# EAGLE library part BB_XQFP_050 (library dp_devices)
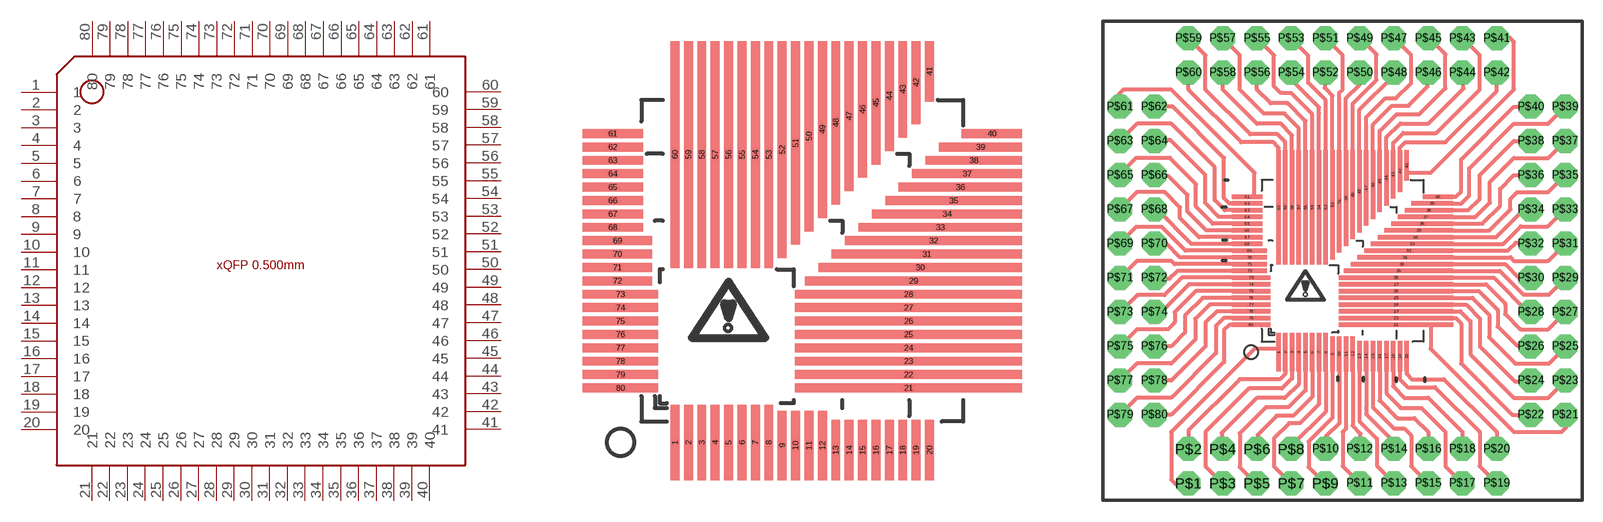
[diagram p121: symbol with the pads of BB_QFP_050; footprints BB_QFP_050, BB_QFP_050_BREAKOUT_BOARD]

Designator prefix -

## BB_XQFP_050  [BB_QFP_050]
1  1
2  2
3  3
4  4
5  5
6  6
7  7
8  8
9  9
10  10
11  11
12  12
13  13
14  14
15  15
16  16
17  17
18  18
19  19
20  20
21  21
22  22
23  23
24  24
25  25
26  26
27  27
28  28
29  29
30  30
31  31
32  32
33  33
34  34
35  35
36  36
37  37
38  38
39  39
40  40
41  41
42  42
43  43
44  44
45  45
46  46
47  47
48  48
49  49
50  50
51  51
52  52
53  53
54  54
55  55
56  56
57  57
58  58
59  59
60  60
61  61
62  62
63  63
64  64
65  65
66  66
67  67
68  68
69  69
70  70
71  71
72  72
73  73
74  74
75  75
76  76
77  77
78  78
79  79
80  80

## BB_XQFP_050BB  [BB_QFP_050_BREAKOUT_BOARD]
P$1  1
P$2  2
P$3  3
P$4  4
P$5  5
P$6  6
P$7  7
P$8  8
P$9  9
P$10  10
P$11  11
P$12  12
P$13  13
P$14  14
P$15  15
P$16  16
P$17  17
P$18  18
P$19  19
P$20  20
P$21  21
P$22  22
P$23  23
P$24  24
P$25  25
P$26  26
P$27  27
P$28  28
P$29  29
P$30  30
P$31  31
P$32  32
P$33  33
P$34  34
P$35  35
P$36  36
P$37  37
P$38  38
P$39  39
P$40  40
P$41  41
P$42  42
P$43  43
P$44  44
P$45  45
P$46  46
P$47  47
P$48  48
P$49  49
P$50  50
P$51  51
P$52  52
P$53  53
P$54  54
P$55  55
P$56  56
P$57  57
P$58  58
P$59  59
P$60  60
P$61  61
P$62  62
P$63  63
P$64  64
P$65  65
P$66  66
P$67  67
P$68  68
P$69  69
P$70  70
P$71  71
P$72  72
P$73  73
P$74  74
P$75  75
P$76  76
P$77  77
P$78  78
P$79  79
P$80  80

## Footprint BB_QFP_050 (pad centres in mm)
QFP 0.5 mm pitch 32p (5mm sq) 48p (7mm sq) 64p (10mm sq) 80p (12mm sq) CC-BY-SA
smd 0.33 x 2.824: 1 -4.75,-6.788; 2 -4.25,-6.788; 3 -3.75,-6.788; 4 -3.25,-6.788; 5 -2.75,-6.788; 6 -2.25,-6.788; 7 -1.75,-6.788; 8 -1.25,-6.788
smd 0.33 x 2.6: 9 -0.75,-6.9; 10 -0.25,-6.9; 11 0.25,-6.9; 12 0.75,-6.9
smd 0.33 x 2.25: 13 1.25,-7.075; 14 1.75,-7.075; 15 2.25,-7.075; 16 2.75,-7.075; 17 3.25,-7.075; 18 3.75,-7.075; 19 4.25,-7.075; 20 4.75,-7.075; 41 4.75,7.075
smd 8.47 x 0.33: 21 3.965,-4.75; 22 3.965,-4.25; 23 3.965,-3.75; 24 3.965,-3.25; 25 3.965,-2.75; 26 3.965,-2.25; 27 3.965,-1.75; 28 3.965,-1.25
smd 8.1 x 0.33: 29 4.15,-0.75
smd 7.6 x 0.33: 30 4.4,-0.25
smd 7.1 x 0.33: 31 4.65,0.25
smd 6.6 x 0.33: 32 4.9,0.75
smd 6.1 x 0.33: 33 5.15,1.25
smd 5.6 x 0.33: 34 5.4,1.75
smd 5.1 x 0.33: 35 5.65,2.25
smd 4.6 x 0.33: 36 5.9,2.75
smd 4.1 x 0.33: 37 6.15,3.25
smd 3.6 x 0.33: 38 6.4,3.75
smd 3.1 x 0.33: 39 6.65,4.25
smd 2.25 x 0.33: 40 7.075,4.75; 61 -7.075,4.75; 62 -7.075,4.25; 63 -7.075,3.75; 64 -7.075,3.25; 65 -7.075,2.75; 66 -7.075,2.25; 67 -7.075,1.75; 68 -7.075,1.25
smd 0.33 x 3.1: 42 4.25,6.65
smd 0.33 x 3.6: 43 3.75,6.4
smd 0.33 x 4.1: 44 3.25,6.15
smd 0.33 x 4.6: 45 2.75,5.9
smd 0.33 x 5.1: 46 2.25,5.65
smd 0.33 x 5.6: 47 1.75,5.4
smd 0.33 x 6.1: 48 1.25,5.15
smd 0.33 x 6.6: 49 0.75,4.9
smd 0.33 x 7.1: 50 0.25,4.65
smd 0.33 x 7.6: 51 -0.25,4.4
smd 0.33 x 8.1: 52 -0.75,4.15
smd 0.33 x 8.47: 53 -1.25,3.965; 54 -1.75,3.965; 55 -2.25,3.965; 56 -2.75,3.965; 57 -3.25,3.965; 58 -3.75,3.965; 59 -4.25,3.965; 60 -4.75,3.965
smd 2.6 x 0.33: 69 -6.9,0.75; 70 -6.9,0.25; 71 -6.9,-0.25; 72 -6.9,-0.75
smd 2.824 x 0.33: 73 -6.788,-1.25; 74 -6.788,-1.75; 75 -6.788,-2.25; 76 -6.788,-2.75; 77 -6.788,-3.25; 78 -6.788,-3.75; 79 -6.788,-4.25; 80 -6.788,-4.75

## Footprint BB_QFP_050_BREAKOUT_BOARD (pad centres in mm)
QFP 0.5 mm pitch 32p (5mm sq) 48p (7mm sq) 64p (10mm sq) 80p (12mm sq) CC-BY-SA
smd 0.33 x 2.824: 1 -4.75,-6.788; 2 -4.25,-6.788; 3 -3.75,-6.788; 4 -3.25,-6.788; 5 -2.75,-6.788; 6 -2.25,-6.788; 7 -1.75,-6.788; 8 -1.25,-6.788
smd 0.33 x 2.6: 9 -0.75,-6.9; 10 -0.25,-6.9; 11 0.25,-6.9; 12 0.75,-6.9
smd 0.33 x 2.25: 13 1.25,-7.075; 14 1.75,-7.075; 15 2.25,-7.075; 16 2.75,-7.075; 17 3.25,-7.075; 18 3.75,-7.075; 19 4.25,-7.075; 20 4.75,-7.075; 41 4.75,7.075
smd 8.47 x 0.33: 21 3.965,-4.75; 22 3.965,-4.25; 23 3.965,-3.75; 24 3.965,-3.25; 25 3.965,-2.75; 26 3.965,-2.25; 27 3.965,-1.75; 28 3.965,-1.25
smd 8.1 x 0.33: 29 4.15,-0.75
smd 7.6 x 0.33: 30 4.4,-0.25
smd 7.1 x 0.33: 31 4.65,0.25
smd 6.6 x 0.33: 32 4.9,0.75
smd 6.1 x 0.33: 33 5.15,1.25
smd 5.6 x 0.33: 34 5.4,1.75
smd 5.1 x 0.33: 35 5.65,2.25
smd 4.6 x 0.33: 36 5.9,2.75
smd 4.1 x 0.33: 37 6.15,3.25
smd 3.6 x 0.33: 38 6.4,3.75
smd 3.1 x 0.33: 39 6.65,4.25
smd 2.25 x 0.33: 40 7.075,4.75; 61 -7.075,4.75; 62 -7.075,4.25; 63 -7.075,3.75; 64 -7.075,3.25; 65 -7.075,2.75; 66 -7.075,2.25; 67 -7.075,1.75; 68 -7.075,1.25
smd 0.33 x 3.1: 42 4.25,6.65
smd 0.33 x 3.6: 43 3.75,6.4
smd 0.33 x 4.1: 44 3.25,6.15
smd 0.33 x 4.6: 45 2.75,5.9
smd 0.33 x 5.1: 46 2.25,5.65
smd 0.33 x 5.6: 47 1.75,5.4
smd 0.33 x 6.1: 48 1.25,5.15
smd 0.33 x 6.6: 49 0.75,4.9
smd 0.33 x 7.1: 50 0.25,4.65
smd 0.33 x 7.6: 51 -0.25,4.4
smd 0.33 x 8.1: 52 -0.75,4.15
smd 0.33 x 8.47: 53 -1.25,3.965; 54 -1.75,3.965; 55 -2.25,3.965; 56 -2.75,3.965; 57 -3.25,3.965; 58 -3.75,3.965; 59 -4.25,3.965; 60 -4.75,3.965
smd 2.6 x 0.33: 69 -6.9,0.75; 70 -6.9,0.25; 71 -6.9,-0.25; 72 -6.9,-0.75
smd 2.824 x 0.33: 73 -6.788,-1.25; 74 -6.788,-1.75; 75 -6.788,-2.25; 76 -6.788,-2.75; 77 -6.788,-3.25; 78 -6.788,-3.75; 79 -6.788,-4.25; 80 -6.788,-4.75
drill 1.016 pad 1.778 octagon: P$1 -11.43,-16.51; P$2 -11.43,-13.97; P$3 -8.89,-16.51; P$4 -8.89,-13.97; P$5 -6.35,-16.51; P$6 -6.35,-13.97; P$7 -3.81,-16.51; P$8 -3.81,-13.97; P$9 -1.27,-16.51; P$10 -1.27,-13.97; P$11 1.27,-16.51; P$12 1.27,-13.97; P$13 3.81,-16.51; P$14 3.81,-13.97; P$15 6.35,-16.51; P$16 6.35,-13.97; P$17 8.89,-16.51; P$18 8.89,-13.97; P$19 11.43,-16.51; P$20 11.43,-13.97; P$21 16.51,-11.43; P$22 13.97,-11.43; P$23 16.51,-8.89; P$24 13.97,-8.89; P$25 16.51,-6.35; P$26 13.97,-6.35; P$27 16.51,-3.81; P$28 13.97,-3.81; P$29 16.51,-1.27; P$30 13.97,-1.27; P$31 16.51,1.27; P$32 13.97,1.27; P$33 16.51,3.81; P$34 13.97,3.81; P$35 16.51,6.35; P$36 13.97,6.35; P$37 16.51,8.89; P$38 13.97,8.89; P$39 16.51,11.43; P$40 13.97,11.43; P$41 11.43,16.51; P$42 11.43,13.97; P$43 8.89,16.51; P$44 8.89,13.97; P$45 6.35,16.51; P$46 6.35,13.97; P$47 3.81,16.51; P$48 3.81,13.97; P$49 1.27,16.51; P$50 1.27,13.97; P$51 -1.27,16.51; P$52 -1.27,13.97; P$53 -3.81,16.51; P$54 -3.81,13.97; P$55 -6.35,16.51; P$56 -6.35,13.97; P$57 -8.89,16.51; P$58 -8.89,13.97; P$59 -11.43,16.51; P$60 -11.43,13.97; P$61 -16.51,11.43; P$62 -13.97,11.43; P$63 -16.51,8.89; P$64 -13.97,8.89; P$65 -16.51,6.35; P$66 -13.97,6.35; P$67 -16.51,3.81; P$68 -13.97,3.81; P$69 -16.51,1.27; P$70 -13.97,1.27; P$71 -16.51,-1.27; P$72 -13.97,-1.27; P$73 -16.51,-3.81; P$74 -13.97,-3.81; P$75 -16.51,-6.35; P$76 -13.97,-6.35; P$77 -16.51,-8.89; P$78 -13.97,-8.89; P$79 -16.51,-11.43; P$80 -13.97,-11.43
